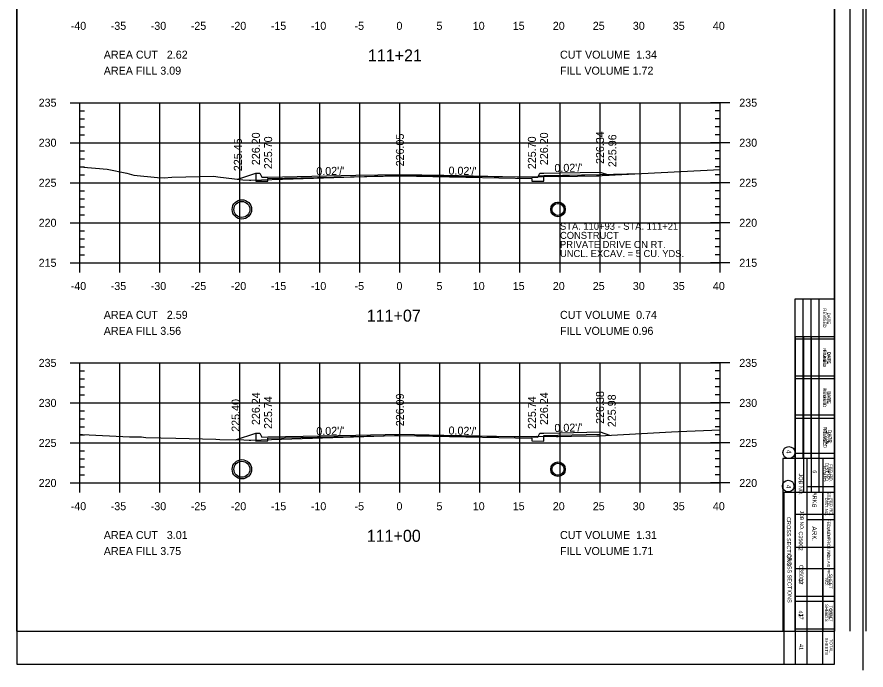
# Model space of a CAD drawing. Extents: x 1367903 to 1373764, y 376865 to 382130.
# Drawn here: x 1372600.2 to 1372812.4, y 377279.1 to 377442.3 of the extents above; entities that cross this region are included whole.
import ezdxf

# ---------------------------------------------------------------- set-up
doc = ezdxf.new("R2010")
doc.units = 0
for name, color, linetype in [('R_Axis', 7, 'Continuous'), ('R_Axis Annot', 7, 'Continuous'), ('R_Border', 7, 'Continuous'), ('R_Border Notes', 7, 'Continuous'), ('R_Border PE', 7, 'Continuous'), ('R_Draft', 7, 'Continuous'), ('R_Drive', 7, 'Continuous'), ('R_Exist Surface', 7, 'Continuous'), ('R_Fin Surface', 7, 'Continuous'), ('R_Fin Surface Annot', 7, 'Continuous'), ('R_Grid', 7, 'Continuous'), ('R_Water', 7, 'Continuous')]:
    doc.layers.add(name, color=color, linetype=linetype)

msp = doc.modelspace()

# ---------------------------------------------------------------- linework, layer by layer
for points in [[(1372659.92, 377403.24), (1372659.92, 377402.58), (1372659.92, 377402.58), (1372659.92, 377401.21), (1372662.92, 377401.27), (1372662.92, 377401.94), (1372695.92, 377402.6), (1372728.92, 377401.94), (1372728.92, 377401.27), (1372731.92, 377401.21), (1372731.92, 377402.66), (1372745.92, 377402.94), (1372745.92, 377403.52)], [(1372659.92, 377338.32), (1372659.92, 377337.65), (1372659.92, 377337.65), (1372659.92, 377336.29), (1372662.92, 377336.35), (1372662.92, 377337.01), (1372695.92, 377337.67), (1372728.92, 377337.01), (1372728.92, 377336.35), (1372731.92, 377336.29), (1372731.92, 377337.73), (1372745.92, 377338.01), (1372745.92, 377338.6)]]:
    msp.add_lwpolyline(points)
at = {"layer": 'R_Axis'}
for p, q in [((1372613.52, 377420.84), (1372618.32, 377420.84)), ((1372615.92, 377380.84), (1372615.92, 377420.84)), ((1372778.32, 377420.84), (1372773.52, 377420.84)), ((1372775.92, 377380.84), (1372775.92, 377420.84)), ((1372615.92, 377418.84), (1372617.12, 377418.84)), ((1372775.92, 377418.84), (1372774.72, 377418.84)), ((1372615.92, 377416.84), (1372617.12, 377416.84)), ((1372775.92, 377416.84), (1372774.72, 377416.84)), ((1372615.92, 377414.84), (1372617.12, 377414.84)), ((1372775.92, 377414.84), (1372774.72, 377414.84)), ((1372615.92, 377412.84), (1372617.12, 377412.84)), ((1372775.92, 377412.84), (1372774.72, 377412.84)), ((1372613.52, 377410.84), (1372618.32, 377410.84)), ((1372778.32, 377410.84), (1372773.52, 377410.84)), ((1372615.92, 377408.84), (1372617.12, 377408.84)), ((1372615.92, 377406.84), (1372617.12, 377406.84)), ((1372775.92, 377408.84), (1372774.72, 377408.84)), ((1372775.92, 377406.84), (1372774.72, 377406.84)), ((1372615.92, 377404.84), (1372617.12, 377404.84)), ((1372775.92, 377404.84), (1372774.72, 377404.84)), ((1372615.92, 377402.84), (1372617.12, 377402.84)), ((1372775.92, 377402.84), (1372774.72, 377402.84)), ((1372613.52, 377400.84), (1372618.32, 377400.84)), ((1372778.32, 377400.84), (1372773.52, 377400.84)), ((1372615.92, 377398.84), (1372617.12, 377398.84)), ((1372775.92, 377398.84), (1372774.72, 377398.84)), ((1372615.92, 377396.84), (1372617.12, 377396.84)), ((1372775.92, 377396.84), (1372774.72, 377396.84)), ((1372615.92, 377394.84), (1372617.12, 377394.84)), ((1372775.92, 377394.84), (1372774.72, 377394.84)), ((1372615.92, 377392.84), (1372617.12, 377392.84)), ((1372775.92, 377392.84), (1372774.72, 377392.84)), ((1372613.52, 377390.84), (1372618.32, 377390.84)), ((1372778.32, 377390.84), (1372773.52, 377390.84)), ((1372615.92, 377388.84), (1372617.12, 377388.84)), ((1372775.92, 377388.84), (1372774.72, 377388.84)), ((1372615.92, 377386.84), (1372617.12, 377386.84)), ((1372775.92, 377386.84), (1372774.72, 377386.84)), ((1372615.92, 377384.84), (1372617.12, 377384.84)), ((1372775.92, 377384.84), (1372774.72, 377384.84)), ((1372615.92, 377378.44), (1372615.92, 377383.24)), ((1372615.92, 377382.84), (1372617.12, 377382.84)), ((1372625.92, 377378.44), (1372625.92, 377383.24)), ((1372635.92, 377378.44), (1372635.92, 377383.24)), ((1372645.92, 377378.44), (1372645.92, 377383.24)), ((1372655.92, 377378.44), (1372655.92, 377383.24)), ((1372665.92, 377378.44), (1372665.92, 377383.24)), ((1372675.92, 377378.44), (1372675.92, 377383.24)), ((1372685.92, 377378.44), (1372685.92, 377383.24)), ((1372695.92, 377378.44), (1372695.92, 377383.24)), ((1372705.92, 377378.44), (1372705.92, 377383.24)), ((1372715.92, 377378.44), (1372715.92, 377383.24)), ((1372725.92, 377378.44), (1372725.92, 377383.24)), ((1372735.92, 377378.44), (1372735.92, 377383.24)), ((1372745.92, 377378.44), (1372745.92, 377383.24)), ((1372755.92, 377378.44), (1372755.92, 377383.24)), ((1372765.92, 377378.44), (1372765.92, 377383.24)), ((1372775.92, 377382.84), (1372774.72, 377382.84)), ((1372775.92, 377378.44), (1372775.92, 377383.24)), ((1372613.52, 377380.84), (1372618.32, 377380.84)), ((1372615.92, 377380.84), (1372775.92, 377380.84)), ((1372778.32, 377380.84), (1372773.52, 377380.84)), ((1372613.52, 377355.84), (1372618.32, 377355.84)), ((1372615.92, 377325.84), (1372615.92, 377355.84)), ((1372615.92, 377353.84), (1372617.12, 377353.84)), ((1372778.32, 377355.84), (1372773.52, 377355.84)), ((1372775.92, 377353.84), (1372774.72, 377353.84)), ((1372775.92, 377325.84), (1372775.92, 377355.84)), ((1372615.92, 377351.84), (1372617.12, 377351.84)), ((1372775.92, 377351.84), (1372774.72, 377351.84)), ((1372615.92, 377349.84), (1372617.12, 377349.84)), ((1372775.92, 377349.84), (1372774.72, 377349.84)), ((1372615.92, 377347.84), (1372617.12, 377347.84)), ((1372775.92, 377347.84), (1372774.72, 377347.84)), ((1372613.52, 377345.84), (1372618.32, 377345.84)), ((1372778.32, 377345.84), (1372773.52, 377345.84)), ((1372615.92, 377343.84), (1372617.12, 377343.84)), ((1372775.92, 377343.84), (1372774.72, 377343.84)), ((1372615.92, 377341.84), (1372617.12, 377341.84)), ((1372775.92, 377341.84), (1372774.72, 377341.84)), ((1372615.92, 377339.84), (1372617.12, 377339.84)), ((1372775.92, 377339.84), (1372774.72, 377339.84)), ((1372615.92, 377337.84), (1372617.12, 377337.84)), ((1372775.92, 377337.84), (1372774.72, 377337.84)), ((1372613.52, 377335.84), (1372618.32, 377335.84)), ((1372778.32, 377335.84), (1372773.52, 377335.84)), ((1372615.92, 377333.84), (1372617.12, 377333.84)), ((1372775.92, 377333.84), (1372774.72, 377333.84)), ((1372615.92, 377331.84), (1372617.12, 377331.84)), ((1372775.92, 377331.84), (1372774.72, 377331.84)), ((1372615.92, 377329.84), (1372617.12, 377329.84)), ((1372775.92, 377329.84), (1372774.72, 377329.84)), ((1372615.92, 377323.44), (1372615.92, 377328.24)), ((1372615.92, 377327.84), (1372617.12, 377327.84)), ((1372625.92, 377323.44), (1372625.92, 377328.24)), ((1372635.92, 377323.44), (1372635.92, 377328.24)), ((1372645.92, 377323.44), (1372645.92, 377328.24)), ((1372655.92, 377323.44), (1372655.92, 377328.24)), ((1372665.92, 377323.44), (1372665.92, 377328.24)), ((1372675.92, 377323.44), (1372675.92, 377328.24)), ((1372685.92, 377323.44), (1372685.92, 377328.24)), ((1372695.92, 377323.44), (1372695.92, 377328.24)), ((1372705.92, 377323.44), (1372705.92, 377328.24)), ((1372715.92, 377323.44), (1372715.92, 377328.24)), ((1372725.92, 377323.44), (1372725.92, 377328.24)), ((1372735.92, 377323.44), (1372735.92, 377328.24)), ((1372745.92, 377323.44), (1372745.92, 377328.24)), ((1372755.92, 377323.44), (1372755.92, 377328.24)), ((1372765.92, 377323.44), (1372765.92, 377328.24)), ((1372775.92, 377327.84), (1372774.72, 377327.84)), ((1372775.92, 377323.44), (1372775.92, 377328.24)), ((1372613.52, 377325.84), (1372618.32, 377325.84)), ((1372615.92, 377325.84), (1372775.92, 377325.84)), ((1372778.32, 377325.84), (1372773.52, 377325.84))]:
    msp.add_line(p, q, dxfattribs=at)
at = {"layer": 'R_Border'}
for p, q in [((1372811.59, 377620.35), (1372811.59, 377279.12)), ((1372600.23, 377611.47), (1372600.23, 377280.59)), ((1372804.55, 377280.59), (1372804.55, 377611.47)), ((1372794.74, 377280.59), (1372794.74, 377362.43)), ((1372794.74, 377362.43), (1372804.55, 377362.43)), ((1372794.74, 377362.43), (1372796.77, 377362.43)), ((1372796.77, 377362.43), (1372796.77, 377323.46)), ((1372798.72, 377362.43), (1372798.72, 377323.46)), ((1372800.57, 377362.43), (1372800.57, 377323.46)), ((1372794.74, 377352.62), (1372804.35, 377352.62)), ((1372794.74, 377342.9), (1372804.35, 377342.9)), ((1372794.74, 377333.27), (1372804.35, 377333.27)), ((1372804.55, 377323.46), (1372791.82, 377323.46)), ((1372791.82, 377323.46), (1372791.82, 377280.59)), ((1372797.65, 377280.59), (1372797.65, 377323.46)), ((1372801.63, 377280.59), (1372801.63, 377323.46)), ((1372804.55, 377316.65), (1372797.65, 377316.65)), ((1372804.55, 377309.75), (1372794.74, 377309.75)), ((1372804.55, 377296.24), (1372794.74, 377296.24)), ((1372804.55, 377289.33), (1372794.74, 377289.33)), ((1372600.23, 377280.59), (1372804.55, 377280.59))]:
    msp.add_line(p, q, dxfattribs=at)
msp.add_circle((1372792.96, 377325.07), 1.46, dxfattribs=at)
at = {"layer": 'R_Border PE'}
for p, q in [((1372808.47, 377288.8), (1372808.47, 377610.76)), ((1372812.39, 377288.8), (1372812.39, 377610.76)), ((1372600.23, 377288.8), (1372600.23, 377603.25)), ((1372804.55, 377603.25), (1372804.55, 377288.8)), ((1372794.6, 377371.74), (1372794.6, 377288.8)), ((1372804.55, 377371.74), (1372794.6, 377371.74)), ((1372796.59, 377371.74), (1372796.59, 377331.96)), ((1372798.58, 377371.74), (1372798.58, 377331.96)), ((1372800.57, 377371.74), (1372800.57, 377331.96)), ((1372804.55, 377361.8), (1372794.6, 377361.8)), ((1372804.55, 377351.85), (1372794.6, 377351.85)), ((1372804.55, 377341.91), (1372794.6, 377341.91)), ((1372804.55, 377331.96), (1372791.62, 377331.96)), ((1372791.62, 377331.96), (1372791.62, 377288.8)), ((1372797.59, 377331.96), (1372797.59, 377288.8)), ((1372801.56, 377331.96), (1372801.56, 377288.8)), ((1372797.65, 377325), (1372804.55, 377325)), ((1372794.73, 377318.04), (1372804.55, 377318.04)), ((1372794.73, 377304.51), (1372804.55, 377304.51)), ((1372794.73, 377297.55), (1372804.55, 377297.55)), ((1372600.23, 377288.8), (1372804.55, 377288.8)), ((1372801.66, 377288.8), (1372801.66, 377288.8))]:
    msp.add_line(p, q, dxfattribs=at)
msp.add_circle((1372793.11, 377333.45), 1.49, dxfattribs=at)
at = {"layer": 'R_Drive'}
for p, q in [((1372730.59, 377402.58), (1372745.92, 377402.89)), ((1372745.92, 377402.89), (1372755.92, 377403.14))]:
    msp.add_line(p, q, dxfattribs=at)
at = {"layer": 'R_Exist Surface'}
for points in [[(1372615.92, 377404.83), (1372622.78, 377404.26), (1372627.64, 377403.21), (1372629.45, 377402.73), (1372635.37, 377402.12), (1372637.01, 377402.05), (1372638.89, 377402.24), (1372649.38, 377402.46), (1372650.4, 377402.28), (1372656.65, 377401.61), (1372658.34, 377401.51), (1372658.65, 377401.49), (1372669.22, 377401.82), (1372694.66, 377402.62), (1372710.2, 377402.45), (1372728.67, 377402.33), (1372734.44, 377402.47), (1372735.16, 377402.47), (1372735.21, 377402.47), (1372735.52, 377402.39), (1372745.06, 377402.54), (1372745.34, 377402.55), (1372745.37, 377402.55), (1372745.63, 377402.61), (1372746.42, 377402.65), (1372775.92, 377404.15)], [(1372615.92, 377338), (1372616.64, 377337.96), (1372628.34, 377337.4), (1372631.33, 377337.38), (1372631.82, 377337.28), (1372632.44, 377337.21), (1372639.92, 377337.02), (1372649.88, 377336.75), (1372650.91, 377336.72), (1372656.95, 377336.58), (1372658.23, 377336.53), (1372658.39, 377336.55), (1372658.45, 377336.55), (1372658.45, 377336.55), (1372658.66, 377336.55), (1372694.6, 377337.69), (1372695.58, 377337.68), (1372728.73, 377337.47), (1372730.17, 377337.5), (1372735.02, 377337.47), (1372735.36, 377337.49), (1372735.47, 377337.46), (1372738.8, 377337.51), (1372745.16, 377337.64), (1372745.74, 377337.65), (1372745.76, 377337.65), (1372763.8, 377338.65), (1372765.55, 377338.73), (1372775.92, 377339.09)]]:
    msp.add_lwpolyline(points, dxfattribs=at)
at = {"layer": 'R_Fin Surface'}
for points in [[(1372655.42, 377401.74), (1372659.92, 377403.24), (1372660.92, 377403.24), (1372661.42, 377402.24), (1372662.92, 377402.27), (1372684.92, 377402.71), (1372695.92, 377402.93), (1372706.92, 377402.71), (1372728.92, 377402.27), (1372730.42, 377402.24), (1372730.92, 377403.24), (1372731.92, 377403.24), (1372735.92, 377403.32), (1372745.92, 377403.52), (1372748.25, 377402.75)], [(1372654.86, 377336.63), (1372659.92, 377338.32), (1372660.92, 377338.32), (1372661.42, 377337.32), (1372662.92, 377337.35), (1372684.92, 377337.79), (1372695.92, 377338.01), (1372706.92, 377337.79), (1372728.92, 377337.35), (1372730.42, 377337.32), (1372730.92, 377338.32), (1372731.92, 377338.32), (1372735.92, 377338.4), (1372745.92, 377338.6), (1372748.33, 377337.79)]]:
    msp.add_lwpolyline(points, dxfattribs=at)
at = {"layer": 'R_Grid'}
for p, q in [((1372615.92, 377420.84), (1372775.92, 377420.84)), ((1372615.92, 377380.84), (1372615.92, 377420.84)), ((1372625.92, 377380.84), (1372625.92, 377420.84)), ((1372635.92, 377380.84), (1372635.92, 377420.84)), ((1372645.92, 377380.84), (1372645.92, 377420.84)), ((1372655.92, 377380.84), (1372655.92, 377420.84)), ((1372665.92, 377380.84), (1372665.92, 377420.84)), ((1372675.92, 377380.84), (1372675.92, 377420.84)), ((1372685.92, 377380.84), (1372685.92, 377420.84)), ((1372695.92, 377380.84), (1372695.92, 377420.84)), ((1372705.92, 377380.84), (1372705.92, 377420.84)), ((1372715.92, 377380.84), (1372715.92, 377420.84)), ((1372725.92, 377380.84), (1372725.92, 377420.84)), ((1372735.92, 377380.84), (1372735.92, 377420.84)), ((1372745.92, 377380.84), (1372745.92, 377420.84)), ((1372755.92, 377380.84), (1372755.92, 377420.84)), ((1372765.92, 377380.84), (1372765.92, 377420.84)), ((1372775.92, 377380.84), (1372775.92, 377420.84)), ((1372615.92, 377410.84), (1372775.92, 377410.84)), ((1372615.92, 377400.84), (1372775.92, 377400.84)), ((1372615.92, 377390.84), (1372775.92, 377390.84)), ((1372615.92, 377380.84), (1372775.92, 377380.84)), ((1372615.92, 377355.84), (1372775.92, 377355.84)), ((1372615.92, 377325.84), (1372615.92, 377355.84)), ((1372625.92, 377325.84), (1372625.92, 377355.84)), ((1372635.92, 377325.84), (1372635.92, 377355.84)), ((1372645.92, 377325.84), (1372645.92, 377355.84)), ((1372655.92, 377325.84), (1372655.92, 377355.84)), ((1372665.92, 377325.84), (1372665.92, 377355.84)), ((1372675.92, 377325.84), (1372675.92, 377355.84)), ((1372685.92, 377325.84), (1372685.92, 377355.84)), ((1372695.92, 377325.84), (1372695.92, 377355.84)), ((1372705.92, 377325.84), (1372705.92, 377355.84)), ((1372715.92, 377325.84), (1372715.92, 377355.84)), ((1372725.92, 377325.84), (1372725.92, 377355.84)), ((1372735.92, 377325.84), (1372735.92, 377355.84)), ((1372745.92, 377325.84), (1372745.92, 377355.84)), ((1372755.92, 377325.84), (1372755.92, 377355.84)), ((1372765.92, 377325.84), (1372765.92, 377355.84)), ((1372775.92, 377325.84), (1372775.92, 377355.84)), ((1372615.92, 377345.84), (1372775.92, 377345.84)), ((1372615.92, 377335.84), (1372775.92, 377335.84)), ((1372615.92, 377325.84), (1372775.92, 377325.84))]:
    msp.add_line(p, q, dxfattribs=at)
at = {"layer": 'R_Water'}
for p, q in [((1372656.42, 377396.62), (1372656.42, 377396.57)), ((1372656.42, 377396.2), (1372656.42, 377396.15)), ((1372735.42, 377396.05), (1372735.42, 377396)), ((1372735.42, 377395.72), (1372735.42, 377395.67)), ((1372656.42, 377392.2), (1372656.42, 377392.15)), ((1372735.42, 377392.72), (1372735.42, 377392.67)), ((1372735.42, 377392.38), (1372735.42, 377392.34)), ((1372656.42, 377391.79), (1372656.42, 377391.74)), ((1372656.42, 377331.7), (1372656.42, 377331.66)), ((1372656.42, 377331.29), (1372656.42, 377331.24)), ((1372735.42, 377331.14), (1372735.42, 377331.09)), ((1372735.42, 377330.8), (1372735.42, 377330.75)), ((1372656.42, 377327.29), (1372656.42, 377327.24)), ((1372656.42, 377326.87), (1372656.42, 377326.82)), ((1372735.42, 377327.8), (1372735.42, 377327.75)), ((1372735.42, 377327.47), (1372735.42, 377327.42))]:
    msp.add_line(p, q, dxfattribs=at)
for centre, radius in [((1372656.42, 377394.18), 2.42), ((1372656.42, 377394.18), 2), ((1372735.42, 377394.19), 1.83), ((1372735.42, 377394.19), 1.5), ((1372656.42, 377329.26), 2.42), ((1372656.42, 377329.26), 2), ((1372735.42, 377329.28), 1.83), ((1372735.42, 377329.28), 1.5)]:
    msp.add_circle(centre, radius, dxfattribs=at)

# ---------------------------------------------------------------- texts
at = {"layer": 'R_Axis Annot'}
for s, height, p in [('-40', 2, (1372613.65, 377439.04)), ('-35', 2, (1372623.65, 377439.04)), ('-30', 2, (1372633.65, 377439.04)), ('-25', 2, (1372643.65, 377439.04)), ('-20', 2, (1372653.65, 377439.04)), ('-15', 2, (1372663.65, 377439.04)), ('-10', 2, (1372673.65, 377439.04)), ('-5', 2, (1372684.58, 377439.04)), ('0', 2, (1372695.05, 377439.04)), ('5', 2, (1372705.05, 377439.04)), ('10', 2, (1372714.12, 377439.04)), ('15', 2, (1372724.11, 377439.04)), ('20', 2, (1372734.12, 377439.04)), ('25', 2, (1372744.11, 377439.04)), ('30', 2, (1372754.12, 377439.04)), ('35', 2, (1372764.11, 377439.04)), ('40', 2, (1372774.12, 377439.04)), ('AREA CUT   2.62', 2, (1372621.92, 377431.84)), ('111+21', 3, (1372687.91, 377431.14)), ('CUT VOLUME  1.34', 2, (1372735.92, 377431.84)), ('AREA FILL 3.09', 2, (1372621.92, 377427.84)), ('FILL VOLUME 1.72', 2, (1372735.92, 377427.84)), ('235', 2, (1372605.64, 377419.84)), ('235', 2, (1372780.72, 377419.84)), ('230', 2, (1372605.64, 377409.84)), ('230', 2, (1372780.72, 377409.84)), ('225', 2, (1372605.64, 377399.84)), ('225', 2, (1372780.72, 377399.84)), ('220', 2, (1372605.64, 377389.84)), ('220', 2, (1372780.72, 377389.84)), ('215', 2, (1372605.64, 377379.84)), ('215', 2, (1372780.72, 377379.84)), ('-40', 2, (1372613.65, 377374.04)), ('-35', 2, (1372623.65, 377374.04)), ('-30', 2, (1372633.65, 377374.04)), ('-25', 2, (1372643.65, 377374.04)), ('-20', 2, (1372653.65, 377374.04)), ('-15', 2, (1372663.65, 377374.04)), ('-10', 2, (1372673.65, 377374.04)), ('-5', 2, (1372684.58, 377374.04)), ('0', 2, (1372695.05, 377374.04)), ('5', 2, (1372705.05, 377374.04)), ('10', 2, (1372714.12, 377374.04)), ('15', 2, (1372724.11, 377374.04)), ('20', 2, (1372734.12, 377374.04)), ('25', 2, (1372744.11, 377374.04)), ('30', 2, (1372754.12, 377374.04)), ('35', 2, (1372764.11, 377374.04)), ('40', 2, (1372774.12, 377374.04)), ('AREA CUT   2.59', 2, (1372621.92, 377366.84)), ('111+07', 3, (1372687.63, 377366.14)), ('CUT VOLUME  0.74', 2, (1372735.92, 377366.84)), ('AREA FILL 3.56', 2, (1372621.92, 377362.84)), ('FILL VOLUME 0.96', 2, (1372735.92, 377362.84)), ('235', 2, (1372605.64, 377354.84)), ('235', 2, (1372780.72, 377354.84)), ('230', 2, (1372605.64, 377344.84)), ('230', 2, (1372780.72, 377344.84)), ('225', 2, (1372605.64, 377334.84)), ('225', 2, (1372780.72, 377334.84)), ('220', 2, (1372605.64, 377324.84)), ('220', 2, (1372780.72, 377324.84)), ('-40', 2, (1372613.65, 377319.04)), ('-35', 2, (1372623.65, 377319.04)), ('-30', 2, (1372633.65, 377319.04)), ('-25', 2, (1372643.65, 377319.04)), ('-20', 2, (1372653.65, 377319.04)), ('-15', 2, (1372663.65, 377319.04)), ('-10', 2, (1372673.65, 377319.04)), ('-5', 2, (1372684.58, 377319.04)), ('0', 2, (1372695.05, 377319.04)), ('5', 2, (1372705.05, 377319.04)), ('10', 2, (1372714.12, 377319.04)), ('15', 2, (1372724.11, 377319.04)), ('20', 2, (1372734.12, 377319.04)), ('25', 2, (1372744.11, 377319.04)), ('30', 2, (1372754.12, 377319.04)), ('35', 2, (1372764.11, 377319.04)), ('40', 2, (1372774.12, 377319.04)), ('AREA CUT   3.01', 2, (1372621.92, 377311.84)), ('111+00', 3, (1372687.63, 377311.14)), ('CUT VOLUME  1.31', 2, (1372735.92, 377311.84)), ('AREA FILL 3.75', 2, (1372621.92, 377307.84)), ('FILL VOLUME 1.71', 2, (1372735.92, 377307.84))]:
    msp.add_text(s, height=height, dxfattribs=at).set_placement(p)
at = {"layer": 'R_Border'}
for s, height, p in [('REVISED', 0.778, (1372801.63, 377359.51)), ('DATE', 0.778, (1372802.8, 377358.64)), ('FILMED', 0.778, (1372801.63, 377349.41)), ('DATE', 0.778, (1372802.8, 377348.82)), ('REVISED', 0.875, (1372801.73, 377339.88)), ('DATE', 0.875, (1372802.9, 377339.1)), ('FILMED', 0.778, (1372801.63, 377330.16)), ('DATE', 0.778, (1372802.8, 377329.77)), ('4', 1.17, (1372792.44, 377325.4)), ('DIST.NO.', 0.778, (1372802.12, 377322.19)), ('FED.RD.', 0.778, (1372803.29, 377321.99)), ('6', 1.17, (1372798.91, 377320.63)), ('JOB NO.', 0.875, (1372795.9, 377318.88)), ('ARK.', 1.166, (1372798.91, 377315)), ('STATE', 0.681, (1372802.6, 377314.9)), ('FED.AID PROJ.NO.', 0.6805, (1372802.71, 377308.49)), ('SHEET', 0.681, (1372803.29, 377294.39)), ('NO.', 0.681, (1372802.12, 377293.61)), ('SHEETS', 0.778, (1372802.12, 377287.2)), ('TOTAL', 0.778, (1372803.29, 377286.91))]:
    msp.add_text(s, height=height, rotation=270, dxfattribs=at).set_placement(p)
at = {"layer": 'R_Border Notes'}
for s, height, p in [('CROSS SECTIONS', 0.9945, (1372792.78, 377308.2)), ('C35002', 0.995, (1372795.7, 377305.39)), ('37', 0.995, (1372795.7, 377293.23)), ('41', 0.995, (1372795.7, 377285.62))]:
    msp.add_text(s, height=height, rotation=270, dxfattribs=at).set_placement(p)
at = {"layer": 'R_Border PE'}
for s, height, p in [('REVISED', 0.796, (1372801.65, 377369.47)), ('DATE', 0.796, (1372802.68, 377368.41)), ('FILMED', 0.796, (1372801.65, 377359.12)), ('DATE', 0.796, (1372802.68, 377358.47)), ('REVISED', 0.796, (1372801.65, 377349.57)), ('DATE', 0.796, (1372802.68, 377348.52)), ('FILMED', 0.796, (1372801.65, 377339.23)), ('DATE', 0.796, (1372802.68, 377338.58)), ('4', 1.19, (1372792.51, 377334.12)), ('DIST.NO.', 0.796, (1372802.22, 377330.83)), ('FED.RD.', 0.796, (1372803.25, 377330.52)), ('6', 0.995, (1372799.08, 377329.02)), ('JOB NO.', 0.995, (1372795.6, 377328.19)), ('ARK.', 0.995, (1372799.08, 377323.6)), ('STATE', 0.796, (1372802.66, 377323.66)), ('CROSS SECTIONS', 0.9945, (1372792.61, 377317.35)), ('FED.AID PROJ.NO.', 0.7956, (1372802.66, 377316.88)), ('C35002', 0.995, (1372795.6, 377313.75)), ('SHEET', 0.796, (1372803.17, 377303.09)), ('37', 0.995, (1372795.6, 377301.96)), ('NO.', 0.796, (1372802.14, 377302.11)), ('SHEETS', 0.796, (1372802.14, 377295.62)), ('TOTAL', 0.796, (1372803.17, 377295.23)), ('41', 0.995, (1372795.6, 377293.96))]:
    msp.add_text(s, height=height, rotation=270, dxfattribs=at).set_placement(p)
at = {"layer": 'R_Draft'}
for s, p in [('STA. 110+93 - STA. 111+21', (1372735.92, 377389.09)), ('CONSTRUCT', (1372735.92, 377386.82)), ('PRIVATE DRIVE ON RT.', (1372735.92, 377384.55)), ('UNCL. EXCAV. = 5 CU. YDS.', (1372735.92, 377382.28))]:
    msp.add_text(s, height=1.75, dxfattribs=at).set_placement(p)
at = {"layer": 'R_Fin Surface Annot'}
for s, rotation, p in [('226.20', 90, (1372660.92, 377405.24)), ('226.20', 90, (1372732.92, 377405.24)), ('226.34', 90, (1372746.92, 377405.52)), ('225.45', 90, (1372656.42, 377403.74)), ('225.70', 90, (1372663.98, 377404.24)), ('226.05', 90, (1372696.92, 377404.93)), ('225.70', 90, (1372729.9, 377404.24)), ('225.96', 90, (1372750, 377404.75)), ("0.02'/'", 1.1458, (1372675.05, 377402.72)), ("0.02'/'", 358.8542, (1372708.05, 377402.89)), ("0.02'/'", 1.1458, (1372734.55, 377403.5)), ('226.24', 90, (1372660.92, 377340.32)), ('225.74', 90, (1372663.98, 377339.32)), ('226.09', 90, (1372696.92, 377340.01)), ('225.74', 90, (1372729.9, 377339.32)), ('226.24', 90, (1372732.92, 377340.32)), ('226.38', 90, (1372746.92, 377340.6)), ('225.98', 90, (1372749.86, 377339.79)), ('225.40', 90, (1372655.86, 377338.63)), ("0.02'/'", 1.1458, (1372675.05, 377337.79)), ("0.02'/'", 358.8542, (1372708.05, 377337.96)), ("0.02'/'", 1.1458, (1372734.55, 377338.57))]:
    msp.add_text(s, height=2, rotation=rotation, dxfattribs=at).set_placement(p)

doc.saveas('drawing.dxf')
